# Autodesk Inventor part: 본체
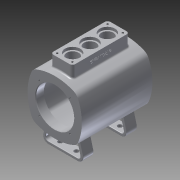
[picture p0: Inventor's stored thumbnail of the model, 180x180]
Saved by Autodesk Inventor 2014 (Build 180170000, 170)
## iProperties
Created: 2015-11
Part Number: 본체
Material: Aluminum 6061
Document SubType Name: Modeling
Designer: mduedu
Density: 2.71 g/cm^3
Mass: 1109.75 g
Surface Area: 1165.94 cm^2
Volume: 409.502 cm^3
Appearance: Aluminum - Flat
Author: mduedu
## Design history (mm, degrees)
sketch "스케치2"
  geometry: L1 (0, 250)-(0, -250); L2 (250, 0)-(-250, 0); L3 (-50, 50)-(50, 50); L4 (50, 50)-(50, -50); L5 (50, -50)-(-50, -50); L6 (-50, -50)-(-50, 50); A1 r 90 centre (-40, 0) between (40.415, -40.415) and (40.415, 40.415); A2 r 90 centre (40, 0) between (-40.415, 40.415) and (-40.415, -40.415); A3 r 90 centre (0, -40) between (40.415, 40.415) and (-40.415, 40.415); A4 r 90 centre (0, 40) between (-40.415, -40.415) and (40.415, -40.415); 2 further points
  constraints: 12 end point, 8 point on circle, 4 centre point, 4 tangent, 3 perpendicular, 2 horizontal alignment, 2 midpoint, 2 parallel, 2 symmetric about line, 1 coincident, 1 equal radius, 1 horizontal, 1 vertical, 1 vertical alignment, 2 other
  dimensions: "d6" = 500 distance of L1.start L1.end; "d8" = 500 distance of L2.start L2.end; "d9" = 100 distance of L3.end L4.end; "d11" = 90 radius of A3
extrude "돌출1" new body sketch "스케치2" stored distance "d12" = 130; taper "d13" = 0 deg
fillet "모깎기6" dims "d30" = 15
feature "쉘1" dims "d31" = 15, "d32" = 6, "d33" = 15
sketch "스케치5"
  geometry: C1 r 35 at (0, 0); 1 further point
  constraints: 1 centre point, 1 coincident
  dimensions: "d34" = 70 diameter of C1
extrude "돌출3" cut sketch "스케치5" stored distance "d36" = 3; taper "d37" = 0 deg
fillet "모깎기14" dims "d78" = 3
sketch "스케치12"
  geometry: L1 (0, 0)-(28.284, 28.284); L2 (0, 0)-(40, 0); A1 r 40 centre (0, 0) between (28.284, 28.284) and (40, 0); 2 further points
  constraints: 4 end point, 2 coincident, 2 point on circle, 1 centre point, 1 horizontal
  dimensions: "d79" = 80 diameter of A1; "d80" = 45 deg angle of L2 L1
hole "구멍2" sketch "스케치12" at (28.284, 28.284) diameter "d82" = 3.242; stored, may be unused: countersink angle "d86" = 90 deg, drill point angle "d88" = 118 deg; dims "d83" = 9, "d84" = 10, "d85" = 2, "d87" = 11
node "작업 평면2"
sketch "스케치13"
  geometry: L1 (-52.5, -20)-(52.5, -20); L2 (52.5, -20)-(52.5, 20); L3 (52.5, 20)-(-52.5, 20); L4 (-52.5, 20)-(-52.5, -20); L5 (-52.5, -20)-(52.5, 20); L6 (52.5, -20)-(-52.5, 20); 1 further point
  constraints: 12 end point, 2 midpoint, 2 parallel, 1 horizontal, 1 perpendicular
  dimensions: "d93" = 105 distance of L2.end L3.end; "d95" = 40 distance of L1.end L2.end
extrude "돌출8" join sketch "스케치13" stored distance "d96" = 80; taper "d97" = 0 deg
fillet "모깎기15" dims "d98" = 5
fillet "모깎기16" dims "d99" = 3
sketch "스케치14"
  geometry: L1 (-52.5, 15)-(-52.5, -15) reference; L2 (52.5, -15)-(52.5, 15) reference; L3 (-52.5, 0)-(52.5, 0); 4 further points
  constraints: 2 end point, 2 midpoint, 2 point on line, 1 coincident
  dimensions: "d100" = 32 distance of point (-32, 0) point (0, 0); "d102" = 32 distance of point (32, 0) point (0, 0) (derived)
hole "구멍3" sketch "스케치14" at (-32, 0), (0, 0), (32, 0) diameter "d103" = 22; stored, may be unused: countersink angle "d107" = 90 deg, drill point angle "d109" = 118 deg; dims "d104" = 8, "d105" = 28, "d106" = 5, "d108" = 10
sketch "스케치15"
  geometry: L1 (46.5, -14)-(-46.5, -14); L2 (-46.5, -14)-(-46.5, 14); L3 (-46.5, 14)-(46.5, 14); L4 (46.5, 14)-(46.5, -14); L5 (46.5, -14)-(-46.5, 14); L6 (-46.5, -14)-(46.5, 14); L7 (47.5, 20)-(-47.5, 20) reference; L8 (-52.5, 15)-(-52.5, -15) reference; 5 further points
  constraints: 12 end point, 4 coincident, 2 midpoint, 2 parallel, 1 horizontal, 1 perpendicular
  dimensions: "d110" = 6 distance between parallel lines of L3 L7; "d111" = 6 distance between parallel lines of L2 L8
hole "구멍4" sketch "스케치15" at (-46.5, 14), (46.5, 14), (46.5, -14), (-46.5, -14) diameter "d112" = 3.242; stored, may be unused: countersink angle "d116" = 90 deg, drill point angle "d118" = 118 deg; dims "d113" = 10, "d114" = 28, "d115" = 5, "d117" = 13
sketch "스케치16"
  geometry: L1 (33.5, 0)-(61.5, 0) reference; 2 further points
  constraints: 1 vertical alignment, 1 other
  dimensions: "d128" = 11 distance from line of L1 point (47.5, -11)
feature "엠보싱2" sketch "스케치16" dims "d6" = 500, "d8" = 500, "d9" = 100, "d11" = 90, "d34" = 70, "d123" = 0.5, "d124" = 0
chamfer "모따기1" distance "d125" = 1; stored, may be unused: second distance "d126" = 2, angle "d127" = 45 deg
sketch "스케치18"
  geometry: L1 (0, 0)-(0, -80); L2 (40, -80)-(30.531, -44.663); L3 (-40, -80)-(-30.531, -44.663); L4 (-40, -80)-(40, -80); A1 r 90 centre (0, 40) between (-34.941, -42.941) and (34.941, -42.941) reference; A2 r 90 centre (0, 40) between (-30.531, -44.663) and (30.531, -44.663)
  constraints: 8 end point, 3 point on circle, 2 symmetric about line, 1 centre point, 1 coincident, 1 midpoint, 1 perpendicular, 1 vertical
  dimensions: "d132" = 80 distance of L3.start L2.start; "d134" = 75 deg angle of L4 L2; "d136" = 80 distance of L1.start L1.end
extrude "돌출9" new body sketch "스케치18" stored distance "d137" = 100; taper "d138" = 0 deg
fillet "모깎기17" dims "d139" = 10
sketch "스케치19"
  geometry: L1 (26.968, -80)-(-26.968, -80) reference; L2 (-36.627, -67.412)-(-30.531, -44.663) reference; L3 (30.531, -44.663)-(36.627, -67.412) reference; L4 (-25.775, -46.23)-(-31.797, -68.706); L5 (-26.968, -75)-(26.968, -75); L6 (31.797, -68.706)-(25.775, -46.23); L7 (0, 0)-(0, -80); A1 r 10 centre (26.968, -70) between (26.968, -80) and (36.627, -67.412) reference; A2 r 10 centre (-26.968, -70) between (-36.627, -67.412) and (-26.968, -80) reference; A3 r 90 centre (0, 40) between (-30.531, -44.663) and (30.531, -44.663) reference; A4 r 5 centre (-26.968, -70) between (-31.797, -68.706) and (-26.968, -75); A5 r 5 centre (26.968, -70) between (26.968, -75) and (31.797, -68.706); A6 r 90 centre (0, 40) between (-25.775, -46.23) and (25.775, -46.23)
  constraints: 8 end point, 7 point on circle, 3 centre point, 2 parallel, 1 coincident, 1 midpoint, 1 symmetric about line, 1 tangent, 2 other
  dimensions: "d140" = 5 distance between parallel lines of L1 L5
extrude "돌출10" cut sketch "스케치19" stored distance "d141" = 100; taper "d142" = 0 deg
sketch "스케치20"
  geometry: L1 (-30, 0)-(30, 0); L2 (30, 0)-(30, -90); L3 (30, -90)-(-30, -90); L4 (-30, -90)-(-30, 0); L5 (50, -80)-(-50, -80) reference; 2 further points
  constraints: 8 end point, 2 parallel, 1 coincident, 1 horizontal, 1 midpoint, 1 perpendicular
  dimensions: "d143" = 10 distance from line of L5 L2.end; "d144" = 60 distance of L2.end L3.end
extrude "돌출11" cut sketch "스케치20" stored distance "d145" = 100; taper "d146" = 0 deg
sketch "스케치21"
  geometry: L1 (0, 26.968)-(100, 26.968); L2 (100, 53.935)-(100, 0) reference; L3 (0, 0)-(0, 53.935) reference; L4 (0, 53.935)-(20, 53.935) reference; L5 (20, 0)-(0, 0) reference; L6 (115, 76.968)-(-15, 76.968) reference; L7 (115, -23.032)-(-15, -23.032) reference; L8 (10, 53.935)-(10, 0); L9 (50, 76.968)-(50, -23.032); C1 r 4 at (10, 41.968); C2 r 4 at (10, 11.968); C3 r 4 at (90, 41.968); C4 r 4 at (90, 11.968); 2 further points
  constraints: 6 end point, 6 midpoint, 4 centre point, 3 symmetric about line, 1 coincident, 1 horizontal, 1 point on line, 3 other
  dimensions: "d147" = 8 diameter of C1; "d148" = 15 distance from line of C1.centre L1
extrude "돌출12" cut sketch "스케치21" stored distance "d149" = 100; taper "d150" = 0 deg
feature "결합2"
  node "솔리드3"
fillet "모깎기18" dims "d151" = 1
fillet "모깎기19" dims "d152" = 2
node "솔리드1"
pattern_circular "원형 패턴1" dims angle "d90" = 360 deg
mirror "대칭3"
node "투영된 루프1"
